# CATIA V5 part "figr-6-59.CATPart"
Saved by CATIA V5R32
Part number: Part1
Bounding box of the stored display mesh (mm): x -50.648 to 50.648, y -72.183 to 72.183, z -40 to 40
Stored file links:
  D:\PROJECTS\Project 2022\CATIA V5 6R 2022\Resources\Part Files\c06_catia_v5_6r2022_prt\figr-6-59.CATPart
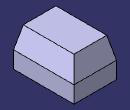
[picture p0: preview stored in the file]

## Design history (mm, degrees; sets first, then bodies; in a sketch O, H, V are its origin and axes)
Body1 (main body)
  Sketch1 on xy-plane, origin (0, 0, 0), H (1, 0, 0), V (0, 1, 0)
    line L1 (-50.6478, 72.1832) -> (50.6478, 72.1832)
    line L2 (50.6478, 72.1832) -> (50.6478, -72.1832)
    line L3 (50.6478, -72.1832) -> (-50.6478, -72.1832)
    line L4 (-50.6478, -72.1832) -> (-50.6478, 72.1832)
    axis line L5 (50.6478, -72.1832) -> (-50.6478, 72.1832)
    horizontal: L1 H, L3 H
    vertical: L2 V, L4 V
    midpoint: O L5
  Pad1: profile Sketch1, direction (0, 0, 1), length 40, mirrored extent
  Draft1: Angle 30, Neutral xy-plane, PullDir (0, 0, 1), SupportToDraft (face of Pad1; face of Pad1)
